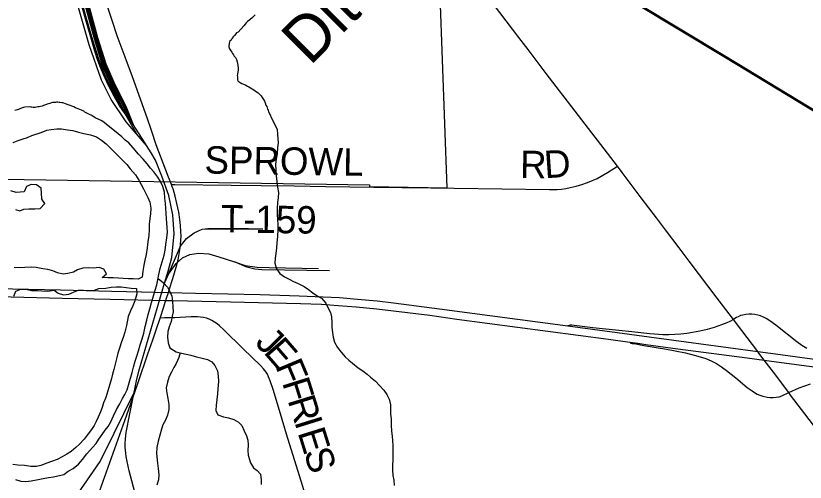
# Model space of a CAD drawing. Extents: x 0 to 34, y 0 to 22.
# Drawn here: x 4.044 to 5.679, y 17.296 to 18.261 of the extents above; entities that cross this region are included whole.
import ezdxf

# ---------------------------------------------------------------- set-up
doc = ezdxf.new("R2010")
doc.units = 0
for name, color, linetype in [('GM_X_Corporation', 7, 'Continuous'), ('GM_X_County_Road', 7, 'Continuous'), ('GM_X_Interchange_Ramps', 7, 'Continuous'), ('GM_X_Major_River', 7, 'Continuous'), ('GM_X_Minor_River', 7, 'Continuous'), ('GM_X_Minor_River_Text', 7, 'Continuous'), ('GM_X_Rail_Line', 7, 'Continuous'), ('GM_X_State_Route', 7, 'Continuous'), ('GM_X_Township_Road', 7, 'Continuous'), ('GM_X_Township_Road_Text', 7, 'Continuous')]:
    doc.layers.add(name, color=color, linetype=linetype)

msp = doc.modelspace()

# ---------------------------------------------------------------- linework, layer by layer
at = {"layer": 'GM_X_Corporation'}
msp.add_lwpolyline([(3.9713, 17.9238), (4.7767, 17.9112), (4.7768, 17.9074), (4.9373, 17.9051), (4.918, 18.4353)], dxfattribs=at)
at = {"layer": 'GM_X_County_Road'}
for points in [[(5.2902, 17.9498), (5.2834, 17.9588), (5.1424, 18.1416), (5.1054, 18.1915), (5.0863, 18.2159), (5.0599, 18.2505), (5.0335, 18.285), (5.0088, 18.3171), (4.9939, 18.3362), (4.9655, 18.3732), (4.9184, 18.4345)], [(4.3668, 17.9115), (4.3625, 17.922), (4.3603, 17.9271), (4.3493, 17.9562), (4.3403, 17.9794), (4.335, 17.994), (4.3254, 18.0235), (4.3162, 18.0499), (4.2856, 18.1348), (4.2704, 18.1756), (4.2543, 18.2194), (4.2443, 18.2489), (4.2346, 18.2784)], [(5.5306, 17.6325), (5.4972, 17.6766), (5.439, 17.7534), (5.4185, 17.7807), (5.3902, 17.8178), (5.3715, 17.8426), (5.3393, 17.8845), (5.3001, 17.9367), (5.2902, 17.9498)], [(4.3534, 17.668), (4.3546, 17.6719), (4.356, 17.6762), (4.3601, 17.6882), (4.3619, 17.6936), (4.3694, 17.7171), (4.3763, 17.7409), (4.3801, 17.7559), (4.3825, 17.7681), (4.3843, 17.7804), (4.3859, 17.7958), (4.3863, 17.805), (4.3862, 17.8143), (4.3855, 17.8267), (4.3841, 17.839), (4.3815, 17.8543), (4.3778, 17.8726), (4.3741, 17.8876), (4.3697, 17.9025), (4.3681, 17.9071), (4.3668, 17.9115)], [(4.3429, 17.6352), (4.3504, 17.6584), (4.3534, 17.668)], [(4.1515, 17.0838), (4.1532, 17.0915), (4.1558, 17.1005), (4.1626, 17.1212), (4.1709, 17.1446), (4.1959, 17.215), (4.2115, 17.259), (4.2458, 17.3557), (4.2563, 17.3849), (4.2697, 17.4231), (4.2865, 17.4699), (4.2977, 17.5022), (4.3173, 17.5613), (4.3279, 17.5905), (4.3351, 17.611), (4.3429, 17.6352)], [(5.6452, 17.4814), (5.6136, 17.5232), (5.5947, 17.548), (5.5835, 17.5627), (5.581, 17.5661), (5.5478, 17.6097), (5.5306, 17.6325)], [(5.733, 17.3514), (5.7308, 17.3567), (5.7273, 17.3643), (5.7229, 17.3724), (5.7186, 17.3805), (5.714, 17.3886), (5.7089, 17.3965), (5.6942, 17.4166), (5.6492, 17.476), (5.6452, 17.4814)]]:
    msp.add_lwpolyline(points, dxfattribs=at)
at = {"layer": 'GM_X_Interchange_Ramps'}
for points in [[(5.5306, 17.6325), (5.5229, 17.6281), (5.5173, 17.6254), (5.5058, 17.621), (5.4911, 17.6161), (5.4763, 17.6117), (5.4613, 17.6081), (5.4462, 17.6051), (5.4339, 17.6032), (5.4217, 17.6018), (5.4093, 17.601), (5.397, 17.6006), (5.3846, 17.6009), (5.3762, 17.601), (5.3675, 17.6017), (5.3574, 17.6028), (5.32, 17.6069), (5.2392, 17.6153), (5.2005, 17.6201), (5.1962, 17.6206), (5.1942, 17.6206), (5.1927, 17.6206), (5.1901, 17.6201), (5.1873, 17.619)], [(5.6828, 17.5722), (5.6723, 17.5786), (5.6622, 17.5858), (5.6184, 17.6203), (5.606, 17.6295), (5.5982, 17.6345), (5.5927, 17.6373), (5.5869, 17.6397), (5.581, 17.6414), (5.575, 17.6426), (5.5688, 17.6431), (5.5626, 17.6431), (5.5564, 17.6426), (5.5503, 17.6415), (5.5454, 17.6403), (5.5403, 17.6382), (5.537, 17.6365), (5.5318, 17.6332), (5.5306, 17.6325)], [(5.3164, 17.5853), (5.3166, 17.5847), (5.3171, 17.5841), (5.3181, 17.5836), (5.3196, 17.5832), (5.3208, 17.583), (5.3283, 17.5817), (5.3448, 17.5788), (5.392, 17.571), (5.4103, 17.5677), (5.4315, 17.5632), (5.4496, 17.5588), (5.4615, 17.5554), (5.4733, 17.5515), (5.4848, 17.5468), (5.4958, 17.5412), (5.5062, 17.5345), (5.5162, 17.5271), (5.5354, 17.5115), (5.5594, 17.4918), (5.5694, 17.4844), (5.5746, 17.481), (5.58, 17.478), (5.5857, 17.4755), (5.5915, 17.4735), (5.5975, 17.472), (5.6005, 17.4714), (5.6067, 17.4708), (5.6129, 17.4708), (5.6191, 17.4713), (5.6252, 17.4725), (5.6311, 17.4742), (5.6452, 17.4814)], [(5.6452, 17.4814), (5.6667, 17.491), (5.6783, 17.4953), (5.6901, 17.4992)]]:
    msp.add_lwpolyline(points, dxfattribs=at)
at = {"layer": 'GM_X_Major_River'}
for points in [[(4.2219, 18.0437), (4.2084, 18.0498), (4.2057, 18.0517), (4.2023, 18.0539), (4.2, 18.055), (4.1977, 18.0562), (4.1927, 18.0588), (4.1901, 18.0603), (4.187, 18.0618), (4.1847, 18.0633), (4.1801, 18.0655), (4.1767, 18.067), (4.1733, 18.0685), (4.171, 18.0692), (4.1679, 18.0707), (4.1645, 18.0722), (4.1603, 18.0741), (4.1565, 18.0755), (4.1523, 18.077), (4.1469, 18.0789), (4.1435, 18.08), (4.1412, 18.0807), (4.1393, 18.0811), (4.1355, 18.0818), (4.1336, 18.0818), (4.131, 18.0821), (4.1283, 18.0821), (4.126, 18.0817), (4.1237, 18.0813), (4.1203, 18.0813), (4.1177, 18.0805), (4.1143, 18.0797), (4.1116, 18.0789), (4.1093, 18.0781), (4.1074, 18.0774), (4.1056, 18.0766), (4.1037, 18.0758), (4.1014, 18.0754), (4.0987, 18.0742), (4.095, 18.0731), (4.0927, 18.0727), (4.0896, 18.0722), (4.087, 18.0718), (4.0843, 18.0714), (4.082, 18.0714), (4.0802, 18.0714), (4.0775, 18.0718), (4.0752, 18.0721), (4.0722, 18.0725), (4.063, 18.072), (4.0596, 18.0712), (4.0555, 18.0696), (4.0524, 18.0685), (4.0498, 18.0673), (4.0475, 18.0665), (4.0445, 18.0657), (4.0418, 18.065)], [(4.0755, 17.2987), (4.0906, 17.3015), (4.1005, 17.3034), (4.1115, 17.305), (4.1218, 17.3066), (4.1437, 17.3117), (4.1528, 17.3182), (4.1627, 17.324), (4.1736, 17.3332), (4.1819, 17.3427), (4.1913, 17.3542), (4.2026, 17.3676), (4.2105, 17.3756), (4.2158, 17.3848), (4.223, 17.3943), (4.229, 17.4031), (4.235, 17.4107), (4.241, 17.4207), (4.2462, 17.4332), (4.2526, 17.4458), (4.2594, 17.458), (4.265, 17.4687), (4.2699, 17.4771), (4.2747, 17.4867), (4.2788, 17.5011), (4.2848, 17.5225), (4.2877, 17.5335), (4.2914, 17.5461), (4.2948, 17.5567), (4.2981, 17.5678), (4.3018, 17.5796), (4.3059, 17.5925), (4.3089, 17.604), (4.3118, 17.6181), (4.3152, 17.631), (4.3185, 17.6424), (4.3218, 17.6542), (4.3252, 17.6676), (4.3296, 17.6832), (4.3326, 17.6931), (4.3359, 17.7041), (4.3385, 17.7144), (4.3403, 17.7255), (4.3433, 17.738), (4.3474, 17.7514), (4.3515, 17.7655), (4.3533, 17.7757), (4.3551, 17.7875), (4.3569, 17.8012), (4.358, 17.813), (4.3575, 17.8229), (4.3562, 17.8408), (4.3554, 17.8518), (4.355, 17.8628), (4.3541, 17.8727), (4.3529, 17.8833), (4.3517, 17.8959), (4.3489, 17.9073), (4.3439, 17.9182), (4.3382, 17.927), (4.3297, 17.9379), (4.3232, 17.9459), (4.316, 17.9546), (4.3079, 17.964), (4.2983, 17.9746), (4.2868, 17.9878), (4.2784, 17.9977), (4.2708, 18.0037), (4.2635, 18.0101), (4.2559, 18.0165), (4.2452, 18.0256), (4.2356, 18.0331), (4.2272, 18.0399), (4.2219, 18.0437)], [(4.0383, 17.9988), (4.0489, 18.0031), (4.0592, 18.0062), (4.0683, 18.0093), (4.0774, 18.0131), (4.0967, 18.0197), (4.108, 18.024), (4.1175, 18.0256), (4.1293, 18.0272), (4.1388, 18.0268), (4.1513, 18.025), (4.1624, 18.0232), (4.1742, 18.0198), (4.1852, 18.0176), (4.1989, 18.0147), (4.2111, 18.0106), (4.2214, 18.0038), (4.2309, 17.9959), (4.2378, 17.9891), (4.247, 17.98), (4.2566, 17.9702), (4.2665, 17.9607), (4.2742, 17.9532), (4.2811, 17.9441), (4.2918, 17.9316), (4.2987, 17.921), (4.3037, 17.9115), (4.3087, 17.9028), (4.3133, 17.8933), (4.3172, 17.8846), (4.3218, 17.8751), (4.3238, 17.863), (4.3227, 17.8512), (4.3217, 17.8417), (4.3202, 17.8295), (4.3203, 17.8189), (4.3193, 17.8063), (4.3178, 17.793), (4.316, 17.7804), (4.3138, 17.7671), (4.3113, 17.7553), (4.3094, 17.7447), (4.3072, 17.7325), (4.3058, 17.7203), (4.2975, 17.7157), (4.2872, 17.7164), (4.2777, 17.7167), (4.2667, 17.717), (4.2568, 17.7177), (4.2454, 17.7188), (4.2344, 17.7183), (4.2226, 17.719), (4.232, 17.7271), (4.2267, 17.7365), (4.2168, 17.7399), (4.2046, 17.7387), (4.1944, 17.739), (4.183, 17.7385), (4.172, 17.7354), (4.1633, 17.7304), (4.1519, 17.7277), (4.1424, 17.7261), (4.1302, 17.7287), (4.1207, 17.7332), (4.11, 17.7358), (4.1002, 17.7373), (4.0865, 17.7398), (4.0758, 17.7405), (4.0629, 17.7397), (4.0508, 17.7396), (4.0409, 17.7399)], [(4.0431, 17.8601), (4.0522, 17.8571), (4.0609, 17.861), (4.0712, 17.8614), (4.0833, 17.8615), (4.0947, 17.8619), (4.1038, 17.8722), (4.0976, 17.8813), (4.0975, 17.8939), (4.0963, 17.9045), (4.0872, 17.9113), (4.0758, 17.9116), (4.0659, 17.9074), (4.0611, 17.8963), (4.0447, 17.8951), (4.0337, 17.8984)], [(4.0398, 17.6806), (4.0443, 17.6909), (4.0545, 17.6951), (4.0651, 17.6948), (4.0765, 17.6926), (4.0887, 17.6927), (4.0982, 17.692), (4.1104, 17.6909), (4.1236, 17.6929), (4.132, 17.6869), (4.1427, 17.6832), (4.1541, 17.6847), (4.1632, 17.6886), (4.1738, 17.6929), (4.184, 17.6929), (4.1954, 17.6922), (4.2072, 17.6934), (4.2163, 17.6962), (4.2304, 17.697), (4.2414, 17.699), (4.2527, 17.7002), (4.2622, 17.7003), (4.2725, 17.6984), (4.2832, 17.6973), (4.2938, 17.6963), (4.295, 17.6853), (4.2906, 17.6712), (4.2861, 17.6605), (4.2816, 17.6506), (4.2771, 17.6384), (4.2731, 17.6201), (4.2697, 17.606), (4.2664, 17.5953), (4.263, 17.5862), (4.2586, 17.5732), (4.2556, 17.563), (4.253, 17.5538), (4.2504, 17.5424), (4.2471, 17.5291), (4.2445, 17.5195), (4.2419, 17.51), (4.239, 17.4982), (4.2345, 17.4845), (4.2304, 17.4712), (4.2259, 17.4597), (4.2226, 17.4502), (4.2192, 17.4411), (4.2147, 17.43), (4.2106, 17.4212), (4.2061, 17.4128), (4.2009, 17.4044), (4.1941, 17.3957), (4.1854, 17.3846), (4.1756, 17.3746), (4.1684, 17.3674), (4.1586, 17.3593), (4.1499, 17.3536), (4.1401, 17.3478), (4.1295, 17.3428), (4.1181, 17.3382), (4.1086, 17.3347), (4.0961, 17.33), (4.0867, 17.3281), (4.0753, 17.328), (4.0619, 17.3298), (4.0483, 17.3309), (4.038, 17.3323)], [(4.0435, 17.3012), (4.0542, 17.2978), (4.0645, 17.2971), (4.0755, 17.2987)]]:
    msp.add_lwpolyline(points, dxfattribs=at)
at = {"layer": 'GM_X_Minor_River'}
for points in [[(4.5399, 18.2627), (4.5343, 18.2574), (4.5286, 18.2528), (4.5241, 18.2489), (4.5211, 18.2466), (4.5192, 18.2439), (4.5166, 18.2401), (4.5045, 18.2274), (4.5015, 18.2255), (4.4996, 18.2236), (4.497, 18.2205), (4.4944, 18.2175), (4.4925, 18.2148), (4.4899, 18.2106), (4.4869, 18.2075), (4.4851, 18.1991), (4.4855, 18.1965), (4.4866, 18.1927), (4.4893, 18.1881), (4.4916, 18.1855), (4.4928, 18.1829), (4.4947, 18.1802), (4.4967, 18.1772), (4.4994, 18.1746), (4.5013, 18.1708), (4.5025, 18.1655), (4.5041, 18.159), (4.5049, 18.1529), (4.5049, 18.1507), (4.5049, 18.1484), (4.5042, 18.1449), (4.5035, 18.1404), (4.5028, 18.1373), (4.5032, 18.1343), (4.5036, 18.1286), (4.5048, 18.1256), (4.5086, 18.1226), (4.5124, 18.1207), (4.5158, 18.1196), (4.5181, 18.1185), (4.5204, 18.1177), (4.5239, 18.1155), (4.5269, 18.114), (4.5304, 18.1117), (4.5338, 18.1099), (4.5372, 18.1076), (4.5407, 18.105), (4.5441, 18.1031), (4.5464, 18.1013), (4.5483, 18.0994), (4.5503, 18.0975), (4.5522, 18.0952), (4.5545, 18.0918), (4.5572, 18.088), (4.5591, 18.0846), (4.5607, 18.0809), (4.5622, 18.0763), (4.5638, 18.0729), (4.565, 18.0703), (4.5657, 18.0676), (4.5665, 18.0653), (4.5673, 18.0631), (4.5766, 18.0435)], [(4.5766, 18.0435), (4.5856, 18.0266), (4.5864, 18.0152), (4.5877, 17.9977), (4.5858, 17.9882), (4.5852, 17.9753), (4.5837, 17.9642), (4.5823, 17.954), (4.5824, 17.9407), (4.5836, 17.9296), (4.5848, 17.9179), (4.586, 17.9065), (4.588, 17.8951), (4.5877, 17.8844), (4.5859, 17.8745), (4.5856, 17.862), (4.5856, 17.8498), (4.5861, 17.8392), (4.5866, 17.8281), (4.5866, 17.8183), (4.5863, 17.8038), (4.5849, 17.7913), (4.5842, 17.781), (4.5824, 17.7688), (4.581, 17.7593), (4.5807, 17.7486), (4.5842, 17.7369), (4.5911, 17.7278), (4.6006, 17.7206), (4.6105, 17.7158), (4.6193, 17.7113), (4.6292, 17.7068), (4.6414, 17.7007), (4.6502, 17.6943), (4.659, 17.6872), (4.6681, 17.6815), (4.6776, 17.6766), (4.6865, 17.6661), (4.6903, 17.657), (4.6961, 17.6471), (4.6977, 17.6376), (4.6989, 17.6262), (4.699, 17.6156), (4.6998, 17.6053), (4.7014, 17.5958), (4.7045, 17.5856), (4.7106, 17.5746), (4.7183, 17.5644), (4.726, 17.5553), (4.7336, 17.5481), (4.7413, 17.5417), (4.7531, 17.5326), (4.7626, 17.5259), (4.7722, 17.5195), (4.7791, 17.5127), (4.789, 17.5047), (4.7978, 17.496), (4.8062, 17.4858), (4.8128, 17.4768), (4.8174, 17.4673), (4.8201, 17.4555), (4.8202, 17.446), (4.8203, 17.4365), (4.8215, 17.4266), (4.8219, 17.4137), (4.8224, 17.4015), (4.824, 17.3909), (4.8244, 17.381), (4.8253, 17.3715), (4.8253, 17.3601), (4.8254, 17.3506), (4.8251, 17.3411), (4.8244, 17.3308), (4.8241, 17.3213), (4.8249, 17.3095), (4.8269, 17.2997), (4.8281, 17.289)], [(4.339, 17.7173), (4.3499, 17.708), (4.358, 17.6993), (4.363, 17.6906), (4.3669, 17.6804), (4.3688, 17.6694), (4.3693, 17.6583), (4.3697, 17.6485), (4.3679, 17.6389), (4.3657, 17.6279), (4.3616, 17.6172), (4.3586, 17.6077), (4.3583, 17.5955), (4.3595, 17.5841), (4.3634, 17.5739), (4.376, 17.5656), (4.3874, 17.5626), (4.3969, 17.5608), (4.4065, 17.5582), (4.4183, 17.5552), (4.43, 17.5523), (4.4411, 17.5493), (4.4499, 17.5444), (4.4564, 17.5372), (4.4621, 17.5259), (4.4634, 17.5156), (4.4642, 17.5038), (4.4628, 17.489), (4.4621, 17.4783), (4.4607, 17.4665), (4.4592, 17.4551), (4.4585, 17.4441), (4.4624, 17.435), (4.4746, 17.4309), (4.4848, 17.4291), (4.4955, 17.4253), (4.5054, 17.4197), (4.5123, 17.4129), (4.5173, 17.4019), (4.5216, 17.3916), (4.5247, 17.3825), (4.5251, 17.3727), (4.5244, 17.3612), (4.5253, 17.3514), (4.5303, 17.3354), (4.5365, 17.3252), (4.5441, 17.3195), (4.551, 17.312), (4.5526, 17.3006), (4.5523, 17.2911)], [(4.3843, 17.5634), (4.3814, 17.5535), (4.3762, 17.5413), (4.3717, 17.5329), (4.3664, 17.5234), (4.3619, 17.5146), (4.3582, 17.5024), (4.3556, 17.4906), (4.3568, 17.4796), (4.3588, 17.4689), (4.3608, 17.4564), (4.3609, 17.4458), (4.3583, 17.4343), (4.3538, 17.4237), (4.3489, 17.4145), (4.3456, 17.4054), (4.3426, 17.3928), (4.3389, 17.3802), (4.3364, 17.3677), (4.3353, 17.3551), (4.3373, 17.335), (4.3389, 17.324), (4.3402, 17.3107), (4.3395, 17.3004), (4.3365, 17.2897)]]:
    msp.add_lwpolyline(points, dxfattribs=at)
at = {"layer": 'GM_X_Rail_Line'}
for p, q in [((4.272, 18.0605), (4.2659, 18.0691)), ((4.2874, 18.036), (4.2797, 18.0484)), ((4.436, 17.82), (4.556, 17.8199))]:
    msp.add_line(p, q, dxfattribs=at)
for points in [[(3.9944, 19.004), (4.0577, 18.9933), (4.0783, 18.989), (4.1192, 18.9788), (4.143, 18.9725), (4.1676, 18.964), (4.2056, 18.9512), (4.2519, 18.9329), (4.3012, 18.9083), (4.3845, 18.8634), (4.4821, 18.8033), (4.6354, 18.7091), (4.8587, 18.5735), (5.1437, 18.3984), (5.5144, 18.1745), (5.855, 17.9684)], [(3.9947, 19.0064), (4.0582, 18.9956), (4.0788, 18.9913), (4.1198, 18.9811), (4.1437, 18.9747), (4.1684, 18.9662), (4.2064, 18.9534), (4.2529, 18.9351), (4.3023, 18.9104), (4.3857, 18.8654), (4.4834, 18.8052), (4.6367, 18.7111), (4.86, 18.5755), (5.1449, 18.4004), (5.5156, 18.1765), (5.8562, 17.9704)], [(4.0948, 18.7161), (4.0995, 18.6609), (4.1089, 18.5939), (4.1225, 18.5458), (4.1632, 18.4003), (4.2133, 18.2162), (4.2302, 18.1615), (4.2491, 18.1188), (4.2721, 18.0736), (4.2874, 18.036)], [(4.0938, 18.6985), (4.097, 18.6606), (4.1065, 18.5934), (4.1201, 18.5451), (4.1608, 18.3996), (4.2109, 18.2155), (4.2278, 18.1606), (4.2468, 18.1177), (4.2698, 18.0725), (4.2797, 18.0484)], [(4.0932, 18.6765), (4.0945, 18.6603), (4.104, 18.5929), (4.1177, 18.5445), (4.1584, 18.399), (4.2085, 18.2148), (4.2255, 18.1598), (4.2446, 18.1166), (4.2676, 18.0715), (4.272, 18.0605)], [(4.2659, 18.0691), (4.2601, 18.0771), (4.2498, 18.0961), (4.2384, 18.1178), (4.2278, 18.1407), (4.2219, 18.1549), (4.2166, 18.1692), (4.2102, 18.1884), (4.2017, 18.2171), (4.1893, 18.2599), (4.171, 18.3261), (4.1443, 18.4258), (4.1317, 18.4687), (4.0957, 18.6004), (4.0941, 18.6221), (4.0933, 18.6432), (4.0931, 18.6524)], [(4.0931, 18.6524), (4.1016, 18.5924), (4.1153, 18.5438), (4.156, 18.3983), (4.2062, 18.2141), (4.2232, 18.1589), (4.2423, 18.1156), (4.2653, 18.0705), (4.2659, 18.0691)], [(4.291, 17.4918), (4.2938, 17.5051), (4.2989, 17.5257), (4.3523, 17.7074), (4.3597, 17.7321), (4.3671, 17.7607), (4.372, 17.8098), (4.3695, 17.8492), (4.3611, 17.8889), (4.3463, 17.9291), (4.3336, 17.9622), (4.3245, 17.9776), (4.3148, 17.9923), (4.2729, 18.0415), (4.2417, 18.0879), (4.2215, 18.1278), (4.1961, 18.2006), (4.1467, 18.3732), (4.1356, 18.4114), (4.1311, 18.4385), (4.1293, 18.4572)], [(4.2937, 18.0171), (4.2705, 18.0583), (4.258, 18.0758), (4.2476, 18.0949), (4.2362, 18.1167), (4.2255, 18.1397), (4.2196, 18.1539), (4.2142, 18.1684), (4.2078, 18.1876), (4.1993, 18.2164), (4.1869, 18.2592), (4.1686, 18.3254), (4.1438, 18.4086), (4.1295, 18.4572)], [(4.2797, 18.0484), (4.2726, 18.0597), (4.272, 18.0605)], [(4.3148, 17.9923), (4.3103, 17.9992), (4.2874, 18.036)], [(4.3602, 17.7262), (4.371, 17.7501), (4.3855, 17.7841), (4.3979, 17.7997), (4.4134, 17.8118), (4.4302, 17.8192), (4.436, 17.82)], [(4.436, 17.82), (4.4467, 17.8216), (4.5259, 17.8209)], [(4.3532, 17.7105), (4.3602, 17.7262), (4.3762, 17.7484), (4.3895, 17.7602), (4.4045, 17.7671), (4.4225, 17.7696), (4.444, 17.7686), (4.4647, 17.7619), (4.4968, 17.7516)], [(4.6936, 17.7328), (4.5535, 17.7351), (4.5389, 17.7368), (4.5227, 17.7405), (4.4968, 17.7516)], [(4.4968, 17.7516), (4.5192, 17.7444), (4.5441, 17.7405), (4.5688, 17.74), (4.6711, 17.7378)], [(4.3728, 16.9624), (4.2846, 17.2983), (4.279, 17.319), (4.2746, 17.3385), (4.2728, 17.3488), (4.2718, 17.3559), (4.2712, 17.3619), (4.2708, 17.3678), (4.2708, 17.3767), (4.2712, 17.3849), (4.2718, 17.3922), (4.2727, 17.3987), (4.2737, 17.4056), (4.2787, 17.43), (4.2882, 17.4783), (4.291, 17.4918)], [(4.164, 17.2599), (4.1914, 17.2987), (4.2191, 17.3382), (4.2481, 17.3974), (4.288, 17.4788)]]:
    msp.add_lwpolyline(points, dxfattribs=at)
at = {"layer": 'GM_X_State_Route'}
for points in [[(4.0032, 17.6965), (4.1368, 17.6935), (4.2425, 17.691), (4.3047, 17.6897), (4.3601, 17.6882), (4.4166, 17.6868), (4.5502, 17.6839), (4.631, 17.6815), (4.6807, 17.6796), (4.7149, 17.6776), (4.752, 17.6747), (4.7923, 17.6709), (4.8262, 17.6671), (4.9218, 17.6546), (5.1873, 17.619), (5.4581, 17.5826), (5.581, 17.5661), (5.6178, 17.5612), (5.7292, 17.5462)], [(3.8813, 17.6826), (3.9256, 17.6818), (4.0343, 17.6791), (4.1399, 17.6767), (4.2393, 17.6743), (4.3546, 17.6719), (4.3697, 17.6716)], [(4.3697, 17.6716), (4.4889, 17.669), (4.6341, 17.6656), (4.6773, 17.6638), (4.7116, 17.6614), (4.7488, 17.6585), (4.7921, 17.6545), (4.8264, 17.6504), (4.9014, 17.6411), (4.9574, 17.6331), (5.2719, 17.5914), (5.3164, 17.5853), (5.3324, 17.5832), (5.3489, 17.5809), (5.4158, 17.5719), (5.5591, 17.5528), (5.5947, 17.548), (5.7232, 17.5309), (5.7298, 17.53)]]:
    msp.add_lwpolyline(points, dxfattribs=at)
at = {"layer": 'GM_X_Township_Road'}
for points in [[(4.3668, 17.9115), (4.3734, 17.9119), (4.4903, 17.9102), (4.5524, 17.9096), (4.6208, 17.9087), (4.686, 17.9077), (4.7854, 17.9064), (4.8444, 17.9057), (4.9035, 17.9049), (4.9375, 17.9046), (4.9522, 17.9044), (5.1498, 17.9014), (5.1653, 17.9017), (5.1746, 17.9023), (5.1837, 17.9036), (5.1928, 17.9054), (5.2048, 17.9084), (5.2167, 17.912), (5.2284, 17.916), (5.2399, 17.9206), (5.2484, 17.9244), (5.2566, 17.9287), (5.2699, 17.9366), (5.2829, 17.945), (5.2902, 17.9498)], [(4.6695, 17.1869), (4.6317, 17.3088), (4.6051, 17.3951), (4.5924, 17.4368), (4.5769, 17.4874), (4.571, 17.5052), (4.5676, 17.5139), (4.5652, 17.5189), (4.5625, 17.5232), (4.5573, 17.53), (4.5509, 17.537), (4.5151, 17.5717), (4.4751, 17.6109), (4.4659, 17.6194), (4.4611, 17.6234), (4.4559, 17.627), (4.4504, 17.6302), (4.4447, 17.6329), (4.4388, 17.635), (4.4326, 17.6365), (4.4264, 17.6373), (4.4201, 17.6377), (4.4076, 17.6376), (4.3734, 17.6361), (4.3517, 17.6355), (4.3429, 17.6352)]]:
    msp.add_lwpolyline(points, dxfattribs=at)

# ---------------------------------------------------------------- texts
at = {"layer": 'GM_X_Minor_River_Text'}
msp.add_text('Ditch', height=0.09475, rotation=45.0015, dxfattribs=at).set_placement((4.6535, 18.1558))
at = {"layer": 'GM_X_Township_Road_Text'}
for s, height, rotation, p in [('SPROWL', 0.05682, 359.1526, (4.4346, 17.9345)), ('R', 0.0568, 358.751, (5.0882, 17.9254)), ('D', 0.0568, 3.9739, (5.1404, 17.9245)), ('T-159', 0.05682, 359.1594, (4.4684, 17.8128)), ('J', 0.0568, 314.971, (4.5375, 17.5822)), ('E', 0.0568, 310.9146, (4.5556, 17.5641)), ('F', 0.0568, 292.7438, (4.5809, 17.536)), ('F', 0.0568, 287.3951, (4.5953, 17.502)), ('R', 0.0568, 287.2778, (4.6067, 17.4654)), ('I', 0.0568, 287.2772, (4.6206, 17.4209)), ('E', 0.0568, 287.2782, (4.6275, 17.3986)), ('S', 0.0568, 287.2757, (4.6401, 17.358))]:
    msp.add_text(s, height=height, rotation=rotation, dxfattribs=at).set_placement(p)

doc.saveas('drawing.dxf')
